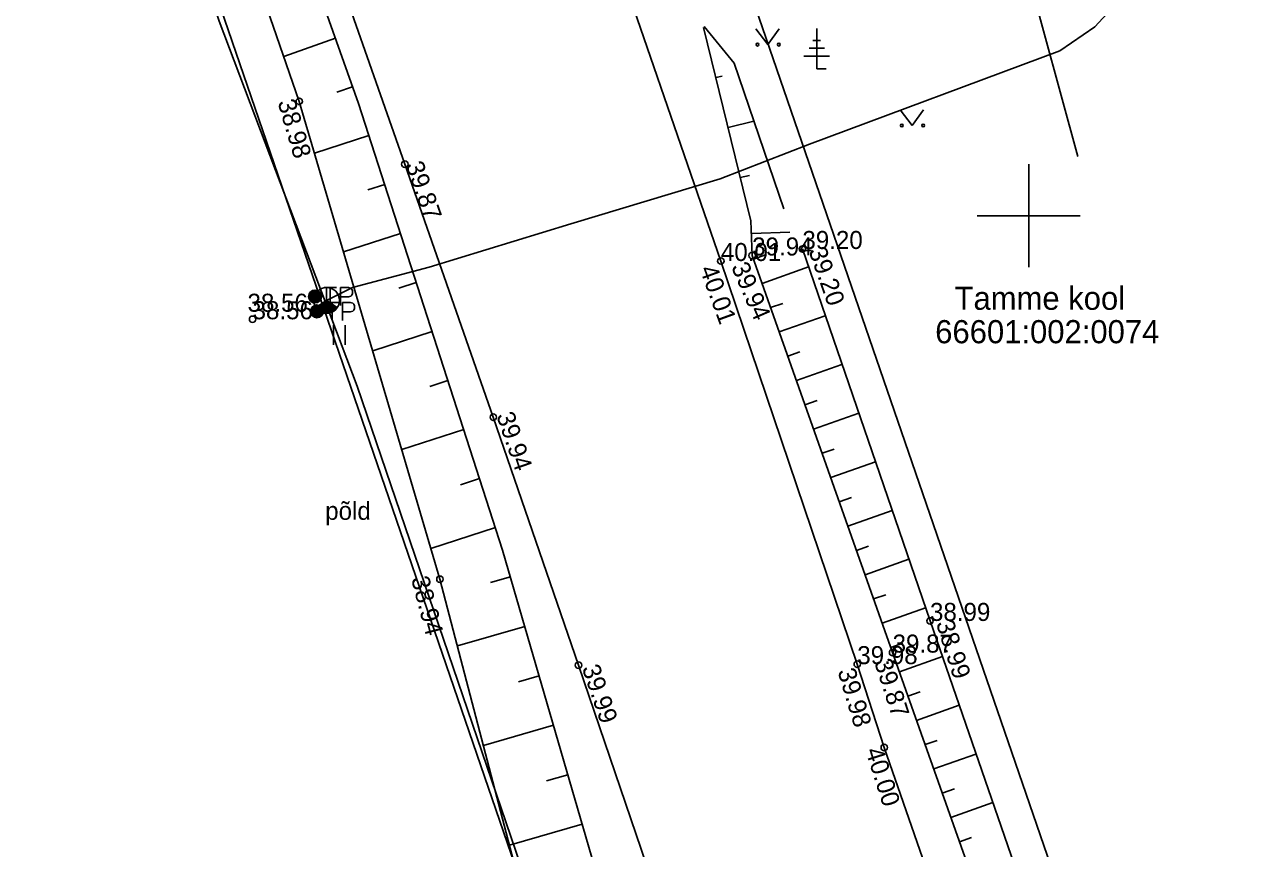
# Model space of a CAD drawing. Extents: x 627548 to 628052, y 6467984 to 6468802.
# Drawn here: x 627961.02 to 628008.99, y 6468025.43 to 6468057.42 of the extents above; entities that cross this region are included whole.
import ezdxf

# ---------------------------------------------------------------- set-up
doc = ezdxf.new("R2010")
doc.units = 0
for name, color, linetype in [('HALJASTUS', 7, 'Continuous'), ('KORGUS-EH2000', 7, 'Continuous'), ('MOOTKORG-EH2000', 7, 'Continuous'), ('MOOTMPUNKT', 7, 'Continuous'), ('MPOHULIIN', 7, 'Continuous'), ('PIIR', 7, 'Continuous'), ('POST', 7, 'Continuous'), ('PUU', 7, 'Continuous'), ('RELJEEF', 7, 'Continuous'), ('SIKAEV', 7, 'Continuous'), ('SITRASS', 7, 'Continuous'), ('TEE', 7, 'Continuous'), ('VORK', 7, 'Continuous')]:
    doc.layers.add(name, color=color, linetype=linetype)

msp = doc.modelspace()

# ---------------------------------------------------------------- linework, layer by layer
at = {"layer": 'HALJASTUS'}
for p, q in [((627989.405, 6468057.255), (627989.868, 6468056.648)), ((627989.868, 6468056.648), (627990.314, 6468057.255)), ((627995.011, 6468054.113), (627995.474, 6468053.507)), ((627995.474, 6468053.507), (627995.92, 6468054.113)), ((627973.005, 6468045.752), (627973.005, 6468044.991)), ((627973.46, 6468045.752), (627973.46, 6468044.991))]:
    msp.add_line(p, q, dxfattribs=at)
for centre in [(627989.467, 6468056.648), (627990.296, 6468056.648), (627995.073, 6468053.507), (627995.902, 6468053.507)]:
    msp.add_circle(centre, 0.055, dxfattribs=at)
at = {"layer": 'KORGUS-EH2000'}
for centre in [(627971.68, 6468054.444), (627975.777, 6468052.007), (627979.213, 6468042.181), (627977.14, 6468035.885), (627982.519, 6468032.549), (627994.391, 6468029.349)]:
    msp.add_circle(centre, 0.125, dxfattribs=at)
at = {"layer": 'MOOTMPUNKT'}
for centre in [(627989.264, 6468048.458), (627991.213, 6468048.711), (627988.048, 6468048.243), (627969.866, 6468045.981), (627996.167, 6468034.265), (627994.715, 6468033.035), (627993.344, 6468032.587)]:
    msp.add_circle(centre, 0.125, dxfattribs=at)
at = {"layer": 'MPOHULIIN'}
msp.add_lwpolyline([(627999.927, 6468059.569), (628001.908, 6468052.307)], dxfattribs=at)
at = {"layer": 'PIIR'}
for p, q in [((627946.33, 6468123.08), (627981.87, 6468019.49)), ((627976.14, 6468096.65), (628002.94, 6468018.71))]:
    msp.add_line(p, q, dxfattribs=at)
at = {"layer": 'POST'}
for p, q in [((627972.652, 6468047.213), (627973.119, 6468047.213)), ((627972.885, 6468047.213), (627972.885, 6468046.513)), ((627973.285, 6468047.213), (627973.285, 6468046.513)), ((627972.725, 6468046.635), (627973.192, 6468046.635)), ((627972.958, 6468046.635), (627972.958, 6468045.935)), ((627973.358, 6468046.635), (627973.358, 6468045.935))]:
    msp.add_line(p, q, dxfattribs=at)
for points in [[(627973.285, 6468047.213), (627973.585, 6468047.213), (627973.685, 6468047.18), (627973.719, 6468047.147), (627973.752, 6468047.08), (627973.752, 6468046.98), (627973.719, 6468046.913), (627973.685, 6468046.88), (627973.585, 6468046.847), (627973.285, 6468046.847)], [(627973.358, 6468046.635), (627973.658, 6468046.635), (627973.758, 6468046.602), (627973.792, 6468046.569), (627973.825, 6468046.502), (627973.825, 6468046.402), (627973.792, 6468046.335), (627973.758, 6468046.302), (627973.658, 6468046.269), (627973.358, 6468046.269)]]:
    msp.add_lwpolyline(points, dxfattribs=at)
for centre, radius in [((627972.293, 6468046.866), 0.25), ((627972.293, 6468046.866), 0.225), ((627972.293, 6468046.866), 0.2), ((627972.293, 6468046.866), 0.175), ((627972.293, 6468046.866), 0.15), ((627972.293, 6468046.866), 0.125), ((627972.293, 6468046.866), 0.1), ((627972.293, 6468046.866), 0.075), ((627972.293, 6468046.866), 0.05), ((627972.293, 6468046.866), 0.025), ((627972.366, 6468046.288), 0.25), ((627972.366, 6468046.288), 0.225), ((627972.366, 6468046.288), 0.2), ((627972.366, 6468046.288), 0.175), ((627972.366, 6468046.288), 0.15), ((627972.366, 6468046.288), 0.125), ((627972.366, 6468046.288), 0.1), ((627972.366, 6468046.288), 0.075), ((627972.366, 6468046.288), 0.05), ((627972.366, 6468046.288), 0.025)]:
    msp.add_circle(centre, radius, dxfattribs=at)
at = {"layer": 'PUU'}
for p, q in [((627991.77, 6468055.705), (627991.77, 6468057.28)), ((627991.92, 6468056.805), (627991.62, 6468056.805)), ((627992.07, 6468056.505), (627991.47, 6468056.505)), ((627992.27, 6468056.205), (627991.27, 6468056.205)), ((627992.13, 6468055.705), (627991.77, 6468055.705))]:
    msp.add_line(p, q, dxfattribs=at)
at = {"layer": 'RELJEEF'}
for p, q in [((627973.08, 6468056.897), (627971.078, 6468056.188)), ((627987.849, 6468055.367), (627988.1, 6468055.428)), ((627973.748, 6468055.012), (627973.141, 6468054.797)), ((627988.326, 6468053.424), (627989.332, 6468053.671)), ((627974.381, 6468053.115), (627972.271, 6468052.434)), ((627988.803, 6468051.482), (627989.155, 6468051.569)), ((627974.995, 6468051.212), (627974.347, 6468051.003)), ((627975.609, 6468049.308), (627973.401, 6468048.596)), ((627989.233, 6468049.308), (627990.731, 6468049.364)), ((627989.314, 6468048.317), (627989.785, 6468048.484)), ((627989.647, 6468047.375), (627991.452, 6468048.013)), ((627976.224, 6468047.405), (627975.546, 6468047.186)), ((627989.98, 6468046.432), (627990.452, 6468046.598)), ((627990.313, 6468045.489), (627992.101, 6468046.121)), ((627976.838, 6468045.502), (627974.53, 6468044.757)), ((627990.647, 6468044.546), (627991.118, 6468044.713)), ((627990.98, 6468043.603), (627992.75, 6468044.229)), ((627977.452, 6468043.598), (627976.745, 6468043.37)), ((627991.313, 6468042.66), (627991.784, 6468042.827)), ((627991.646, 6468041.718), (627993.399, 6468042.337)), ((627978.066, 6468041.695), (627975.659, 6468040.918)), ((627991.98, 6468040.775), (627992.451, 6468040.941)), ((627992.313, 6468039.832), (627994.048, 6468040.445)), ((627978.681, 6468039.792), (627977.944, 6468039.554)), ((627992.646, 6468038.889), (627993.117, 6468039.056)), ((627992.979, 6468037.946), (627994.696, 6468038.553)), ((627979.295, 6468037.888), (627976.789, 6468037.08)), ((627993.312, 6468037.003), (627993.784, 6468037.17)), ((627993.646, 6468036.06), (627995.345, 6468036.661)), ((627979.878, 6468035.975), (627979.108, 6468035.752)), ((627993.979, 6468035.118), (627994.45, 6468035.284)), ((627994.312, 6468034.175), (627995.994, 6468034.769)), ((627980.434, 6468034.054), (627977.817, 6468033.296)), ((627994.645, 6468033.232), (627995.117, 6468033.399)), ((627994.979, 6468032.289), (627996.646, 6468032.878)), ((627980.991, 6468032.133), (627980.19, 6468031.901)), ((627995.312, 6468031.346), (627995.783, 6468031.513)), ((627995.645, 6468030.403), (627997.299, 6468030.988)), ((627981.548, 6468030.212), (627978.828, 6468029.425)), ((627995.978, 6468029.461), (627996.45, 6468029.627)), ((627996.312, 6468028.518), (627997.951, 6468029.097)), ((627982.104, 6468028.292), (627981.273, 6468028.051)), ((627996.645, 6468027.575), (627997.116, 6468027.741)), ((627996.978, 6468026.632), (627998.604, 6468027.207)), ((627982.661, 6468026.371), (627979.84, 6468025.553)), ((627997.311, 6468025.689), (627997.783, 6468025.856))]:
    msp.add_line(p, q, dxfattribs=at)
for points in [[(627978.291, 6468008.882), (627983.457, 6468013.678), (627984.21, 6468021.024), (627979.575, 6468037.02), (627973.979, 6468054.36), (627968.222, 6468070.605), (627961.466, 6468089.433), (627957.405, 6468099.776), (627954.697, 6468099.952), (627954.601, 6468100.77), (627956.677, 6468103.285), (627952.114, 6468117.091), (627946.482, 6468133.262), (627941.383, 6468147.782), (627936.221, 6468162.714), (627931.414, 6468176.011), (627926.765, 6468189.068), (627921.448, 6468202.325), (627917.805, 6468212.302), (627916.173, 6468214.408), (627912.962, 6468214.481), (627910.459, 6468214.182)], [(627910.966, 6468212.647), (627913.157, 6468213.418), (627915.522, 6468212.557), (627919.56, 6468201.376), (627924.571, 6468188.424), (627929.207, 6468175.576), (627934.909, 6468161.365), (627939.161, 6468147.561), (627944.576, 6468131.872), (627949.813, 6468116.897), (627954.804, 6468102.831), (627953.147, 6468101.408), (627953.982, 6468098.417), (627956.488, 6468098.118), (627959.583, 6468088.974), (627966.658, 6468069.004), (627971.68, 6468054.444), (627977.14, 6468035.885), (627981.189, 6468020.389), (627981.639, 6468013.545), (627978.211, 6468009.476)], [(627987.372, 6468057.309), (627989.214, 6468049.808)], [(627987.398, 6468057.353), (627988.562, 6468055.934), (627990.49, 6468050.266)], [(627989.214, 6468049.808), (627989.264, 6468048.458), (627994.715, 6468033.035), (627998.926, 6468021.122), (628002.749, 6468019.088), (628005.556, 6468019.033)], [(627991.213, 6468048.711), (627996.167, 6468034.265), (628000.311, 6468022.262), (628002.878, 6468020.572), (628005.153, 6468020.311)]]:
    msp.add_lwpolyline(points, dxfattribs=at)
at = {"layer": 'SIKAEV'}
for p, q in [((627972.74, 6468047.214), (627972.74, 6468046.714)), ((627972.74, 6468046.714), (627972.325, 6468046.439)), ((627972.74, 6468046.714), (627973.155, 6468046.439))]:
    msp.add_line(p, q, dxfattribs=at)
msp.add_circle((627972.74, 6468046.714), 0.5, dxfattribs=at)
for radius in [0.075, 0.05, 0.475, 0.45, 0.425, 0.4, 0.375, 0.35, 0.325, 0.3, 0.275, 0.25, 0.225, 0.2, 0.175, 0.15, 0.125, 0.1]:
    msp.add_arc((627972.74, 6468046.714), radius, 213.5305, 326.4695, dxfattribs=at)
at = {"layer": 'SITRASS'}
for points in [[(627969.796, 6467996.723), (627973.191, 6467998.006), (627976.323, 6467999.384), (627976.439, 6468000.299), (627974.452, 6468004.589), (627974.615, 6468005.444), (627975.744, 6468006.43), (627979.437, 6468008.95), (627982.801, 6468012.806), (627983.762, 6468016.772), (627983.396, 6468018.821), (627982.465, 6468019.728), (627980.449, 6468024.262), (627973.928, 6468043.378), (627968.573, 6468057.558), (627963.8, 6468071.726), (627958.775, 6468086.331), (627947.216, 6468119.583), (627940.944, 6468137.544)], [(627972.74, 6468046.714), (627973.751, 6468047.209), (627976.725, 6468048.008), (627982.226, 6468049.69), (627988.02, 6468051.44), (627991.483, 6468052.786), (628001.207, 6468056.403), (628002.562, 6468057.339), (628005.253, 6468060.26), (628008.875, 6468064.486), (628008.99, 6468065.414), (628006.811, 6468067.976)]]:
    msp.add_lwpolyline(points, dxfattribs=at)
at = {"layer": 'TEE'}
for points in [[(627948.73, 6468130.073), (627952.157, 6468120.49), (627955.55, 6468110.522), (627958.987, 6468100.641), (627962.318, 6468091.154), (627965.56, 6468081.571), (627969.012, 6468071.605), (627972.432, 6468061.577), (627975.777, 6468052.007), (627979.213, 6468042.181), (627982.519, 6468032.549), (627985.763, 6468023.005), (627987.717, 6468016.784), (627987.108, 6468013.905), (627990.1, 6468007.105), (627992.636, 6468000.403), (627994.498, 6467998.047), (627996.95, 6467991.167)], [(628006.43, 6467993.97), (628003.022, 6468005.387), (628001.133, 6468010.151), (627997.263, 6468021.078), (627994.391, 6468029.349), (627993.344, 6468032.587), (627988.048, 6468048.243), (627983.251, 6468062.182), (627977.119, 6468079.943), (627976.679, 6468084.026), (627984.465, 6468086.573), (627984.734, 6468088.185)]]:
    msp.add_lwpolyline(points, dxfattribs=at)
at = {"layer": 'VORK'}
for p, q in [((628000, 6468052), (628000, 6468048)), ((627998, 6468050), (628002, 6468050))]:
    msp.add_line(p, q, dxfattribs=at)

# ---------------------------------------------------------------- texts
at = {"layer": 'HALJASTUS'}
msp.add_text('põld', height=0.7, dxfattribs=at).set_placement((627972.686, 6468038.192))
at = {"layer": 'KORGUS-EH2000'}
for s, rotation, p in [(' 38.98', 286.3937, (627970.759, 6468054.667)), (' 39.87', 289.2739, (627975.714, 6468052.224)), ('39.20', 289.455, (627991.443, 6468048.649)), ('39.94', 293.4027, (627988.437, 6468048.022)), ('40.01', 289.9412, (627987.216, 6468047.932)), (' 39.94', 288.9438, (627979.239, 6468042.495)), (' 38.94', 284.6436, (627975.951, 6468036.162)), ('38.99', 287.6183, (627996.392, 6468034.183)), ('39.87', 288.0644, (627993.993, 6468032.671)), (' 39.99', 288.7729, (627982.561, 6468032.688)), ('39.98', 286.6769, (627992.573, 6468032.32)), (' 40.00', 287.5123, (627993.576, 6468029.48))]:
    msp.add_text(s, height=0.7, rotation=rotation, dxfattribs=at).set_placement(p)
msp.add_text('38.56', height=0.7, dxfattribs=at).set_placement((627969.671, 6468046.273))
at = {"layer": 'MOOTKORG-EH2000'}
for s, p in [('39.94', (627989.264, 6468048.458)), ('39.20', (627991.213, 6468048.711)), ('40.01', (627988.048, 6468048.243)), ('38.56', (627969.866, 6468045.981)), ('38.99', (627996.167, 6468034.265)), ('39.87', (627994.715, 6468033.035)), ('39.98', (627993.344, 6468032.587))]:
    msp.add_text(s, height=0.7, dxfattribs=at).set_placement(p)
at = {"layer": 'PIIR'}
for s, p in [('Tamme kool', (627997.12, 6468046.349)), ('66601:002:0074', (627996.369, 6468045.049))]:
    msp.add_text(s, height=0.9, dxfattribs=at).set_placement(p)

doc.saveas('drawing.dxf')
